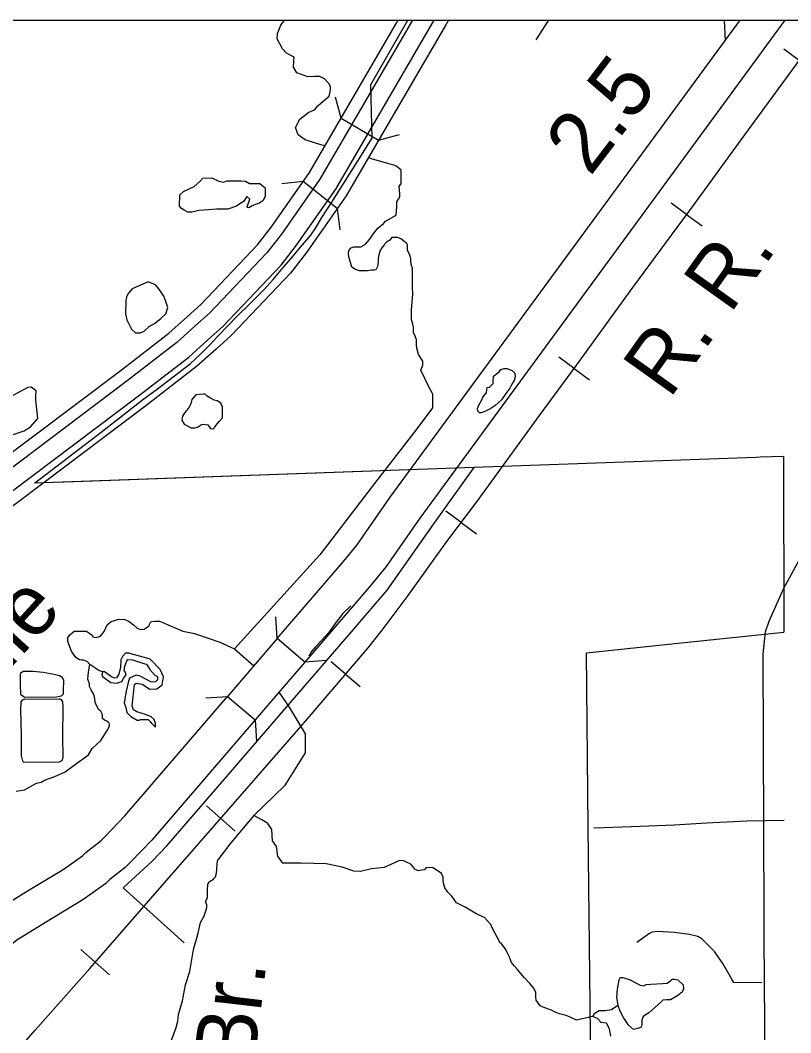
# Model space of a CAD drawing. Extents: x 1367863 to 1368197, y 380048 to 380261.
# Drawn here: x 1367991.45 to 1368012.13, y 380150.28 to 380177.46 of the extents above; entities that cross this region are included whole.
import ezdxf

# ---------------------------------------------------------------- set-up
doc = ezdxf.new("R2010")
doc.units = 0
for name, color, linetype in [('Level 10', 7, 'Continuous'), ('Level 15', 7, 'Continuous'), ('Level 33', 7, 'Continuous'), ('Level 35', 7, 'Continuous'), ('Level 36', 7, 'Continuous'), ('Level 37', 7, 'Continuous'), ('Level 40', 7, 'Continuous'), ('Level 48', 7, 'Continuous'), ('Level 6', 7, 'Continuous'), ('R_No Plot', 7, 'Continuous')]:
    doc.layers.add(name, color=color, linetype=linetype)

msp = doc.modelspace()

# ---------------------------------------------------------------- linework, layer by layer
at = {"layer": 'Level 10'}
for points in [[(1367998.348, 380160.867), (1368000.124, 380162.934), (1368000.494, 380163.382), (1368001.381, 380164.658), (1368010.775, 380177.46)], [(1368011.979, 380177.46), (1368002.171, 380164.093), (1368001.267, 380162.795), (1368000.866, 380162.309), (1367999.084, 380160.235)], [(1368011.429, 380151.097), (1368011.392, 380160.447), (1368011.452, 380161.041), (1368011.552, 380161.327), (1368011.947, 380162.215), (1368012.461, 380163.149), (1368012.59, 380163.421), (1368012.733, 380163.914), (1368013.259, 380165.995), (1368013.574, 380167.366), (1368013.883, 380168.861), (1368014.317, 380170.756)], [(1367998.348, 380160.867), (1367997.013, 380159.313)], [(1367999.084, 380160.235), (1367998.348, 380160.867)], [(1367999.084, 380160.235), (1367997.749, 380158.68)], [(1367988.776, 380151.732), (1367989.071, 380152.078), (1367989.492, 380152.486), (1367989.993, 380152.929), (1367990.793, 380153.566), (1367991.614, 380154.074), (1367992.598, 380154.665), (1367993.114, 380155.031), (1367993.202, 380155.12), (1367993.618, 380155.448), (1367993.715, 380155.544), (1367994.257, 380156.104), (1367997.013, 380159.313)], [(1367997.013, 380159.313), (1367997.749, 380158.68)], [(1367997.749, 380158.68), (1367994.975, 380155.45), (1367994.404, 380154.86), (1367994.26, 380154.719), (1367993.849, 380154.395), (1367993.743, 380154.288), (1367993.129, 380153.852), (1367992.119, 380153.246), (1367991.352, 380152.771), (1367990.618, 380152.186), (1367990.152, 380151.773), (1367989.78, 380151.413), (1367989.515, 380151.102)], [(1368011.429, 380151.098), (1368011.439, 380145.66), (1368011.416, 380141.25), (1368011.392, 380140.52), (1368011.431, 380140.222), (1368011.504, 380139.453), (1368011.603, 380138.92), (1368011.693, 380137.345), (1368011.778, 380132.275), (1368011.845, 380129.756)]]:
    msp.add_lwpolyline(points, dxfattribs=at)
at = {"layer": 'Level 15'}
for points in [[(1367983.775, 380160.267), (1367983.952, 380160.4), (1367986.169, 380162.096), (1367989.568, 380164.62), (1367994.115, 380168.041), (1367995.437, 380169.06), (1367995.925, 380169.499), (1367996.299, 380169.836), (1367997.817, 380171.432), (1367998.192, 380171.917), (1367999.213, 380173.375), (1368001.597, 380177.46)], [(1368001.979, 380177.46), (1367999.491, 380173.197), (1367998.457, 380171.722), (1367998.068, 380171.217), (1367996.529, 380169.599), (1367996.145, 380169.254), (1367995.648, 380168.807), (1367994.315, 380167.778), (1367989.766, 380164.356), (1367986.367, 380161.832), (1367984.151, 380160.136), (1367983.888, 380159.94)], [(1367984.089, 380159.461), (1367984.455, 380159.734), (1367986.671, 380161.43), (1367990.068, 380163.952), (1367994.62, 380167.377), (1367995.971, 380168.419), (1367996.483, 380168.878), (1367996.881, 380169.237), (1367998.451, 380170.888), (1367998.864, 380171.423), (1367999.916, 380172.924), (1368002.563, 380177.46)], [(1368002.944, 380177.46), (1368002.871, 380177.333), (1368000.194, 380172.746), (1367999.13, 380171.227), (1367998.702, 380170.673), (1367997.112, 380169.001), (1367996.703, 380168.633), (1367996.182, 380168.165), (1367994.82, 380167.114), (1367990.266, 380163.688), (1367986.87, 380161.166), (1367984.654, 380159.47), (1367984.225, 380159.15)]]:
    msp.add_lwpolyline(points, dxfattribs=at)
at = {"layer": 'Level 33'}
for points in [[(1368005.626, 380177.46), (1368005.286, 380176.932)], [(1368010.35, 380177.46), (1368010.37, 380176.908)], [(1368011.958, 380155.982), (1368010.959, 380155.964), (1368009.872, 380155.906), (1368009.011, 380155.859), (1368007.86, 380155.807), (1368006.842, 380155.778)], [(1368011.356, 380151.62), (1368010.605, 380151.631), (1368010.553, 380151.719), (1368010.314, 380152.143), (1368010.087, 380152.463), (1368009.75, 380152.806), (1368009.64, 380152.87), (1368009.413, 380152.917), (1368009, 380152.975), (1368008.564, 380153.004), (1368008.413, 380152.981), (1368008.32, 380152.94), (1368008.256, 380152.888), (1368008, 380152.708)]]:
    msp.add_lwpolyline(points, dxfattribs=at)
at = {"layer": 'Level 35'}
for points in [[(1367999.096, 380174.252), (1367998.908, 380174.382), (1367998.833, 380174.585), (1367998.951, 380174.809), (1367999.196, 380174.991), (1367999.325, 380175.044), (1367999.367, 380175.076), (1367999.432, 380175.162), (1367999.581, 380175.29), (1367999.741, 380175.418), (1367999.773, 380175.579), (1367999.773, 380175.685), (1367999.731, 380175.76), (1367999.613, 380175.889), (1367999.485, 380175.953), (1367999.335, 380175.953), (1367999.164, 380175.942), (1367998.876, 380176.049), (1367998.78, 380176.198), (1367998.791, 380176.359), (1367998.801, 380176.466), (1367998.598, 380176.573), (1367998.491, 380176.69), (1367998.342, 380176.957), (1367998.353, 380177.107), (1367998.438, 380177.331), (1367998.538, 380177.46)], [(1367999.62, 380174.089), (1367999.515, 380174.12), (1367999.096, 380174.252)], [(1368001.598, 380172.659), (1368001.639, 380172.72), (1368001.639, 380172.802), (1368001.618, 380173.006), (1368001.67, 380173.067), (1368001.67, 380173.2), (1368001.67, 380173.323), (1368001.67, 380173.435), (1368001.557, 380173.537), (1368001.506, 380173.558), (1368001.251, 380173.629), (1368000.904, 380173.731), (1368000.832, 380173.755)], [(1367997.527, 380172.726), (1367997.453, 380172.603), (1367997.25, 380172.472), (1367997.018, 380172.385), (1367996.916, 380172.385), (1367996.713, 380172.385), (1367996.503, 380172.371), (1367996.242, 380172.349), (1367996.054, 380172.313), (1367995.945, 380172.313), (1367995.843, 380172.364), (1367995.778, 380172.407), (1367995.72, 380172.472), (1367995.734, 380172.77), (1367995.829, 380172.864), (1367996.112, 380173.002), (1367996.264, 380173.133), (1367996.351, 380173.22), (1367996.59, 380173.227), (1367996.779, 380173.14), (1367996.902, 380173.118), (1367996.996, 380173.147), (1367997.149, 380173.147), (1367997.373, 380173.147), (1367997.497, 380173.14), (1367997.598, 380173.082), (1367997.656, 380173.082), (1367997.808, 380173.082), (1367997.881, 380173.075), (1367998.026, 380172.966), (1367998.026, 380172.842), (1367998.019, 380172.726), (1367997.961, 380172.617), (1367997.852, 380172.538), (1367997.75, 380172.516), (1367997.671, 380172.48), (1367997.584, 380172.429), (1367997.555, 380172.436), (1367997.54, 380172.465), (1367997.584, 380172.574), (1367997.613, 380172.654), (1367997.527, 380172.726)], [(1368002.517, 380167.441), (1368002.426, 380167.604), (1368002.201, 380168.072), (1368002.252, 380168.205), (1368002.252, 380168.307), (1368002.139, 380168.491), (1368002.098, 380168.654), (1368002.088, 380168.756), (1368002.088, 380168.879), (1368002.047, 380168.981), (1368002.007, 380169.083), (1368002.007, 380169.226), (1368001.976, 380169.339), (1368001.955, 380169.42), (1368001.955, 380169.553), (1368001.955, 380169.676), (1368001.986, 380170.115), (1368001.976, 380170.299), (1368001.976, 380170.401), (1368001.976, 380170.514), (1368001.976, 380170.616), (1368001.976, 380170.728), (1368001.976, 380170.81), (1368001.955, 380170.881), (1368001.935, 380170.973), (1368001.935, 380171.065), (1368001.904, 380171.157), (1368001.843, 380171.29), (1368001.843, 380171.361), (1368001.843, 380171.433), (1368001.812, 380171.484), (1368001.751, 380171.525), (1368001.68, 380171.586), (1368001.588, 380171.627), (1368001.527, 380171.627), (1368001.486, 380171.627), (1368001.424, 380171.627), (1368001.373, 380171.556), (1368001.281, 380171.504), (1368001.21, 380171.423), (1368001.108, 380171.29), (1368001.077, 380171.167), (1368001.057, 380171.065), (1368001.057, 380170.973), (1368001.036, 380170.851), (1368000.996, 380170.759), (1368000.944, 380170.748), (1368000.873, 380170.748), (1368000.771, 380170.738), (1368000.648, 380170.738), (1368000.556, 380170.738), (1368000.444, 380170.769), (1368000.352, 380170.83), (1368000.322, 380170.932), (1368000.271, 380171.106), (1368000.26, 380171.188), (1368000.271, 380171.28), (1368000.332, 380171.351), (1368000.403, 380171.382), (1368000.516, 380171.382), (1368000.587, 380171.382), (1368000.72, 380171.453), (1368000.822, 380171.576), (1368000.944, 380171.75), (1368001.047, 380171.882), (1368001.2, 380172.005), (1368001.251, 380172.066), (1368001.537, 380172.23), (1368001.557, 380172.454), (1368001.557, 380172.587), (1368001.598, 380172.659)], [(1367994.879, 380170.438), (1367994.451, 380170.249), (1367994.349, 380170.133), (1367994.299, 380170.032), (1367994.284, 380169.93), (1367994.27, 380169.582), (1367994.306, 380169.415), (1367994.429, 380169.169), (1367994.538, 380169.067), (1367994.676, 380169.067), (1367994.77, 380169.118), (1367994.908, 380169.241), (1367995.046, 380169.321), (1367995.22, 380169.459), (1367995.357, 380169.582), (1367995.408, 380169.749), (1367995.357, 380169.909), (1367995.299, 380170.054), (1367995.176, 380170.242), (1367995.075, 380170.358)], [(1367995.075, 380170.358), (1367994.879, 380170.438)], [(1368004.151, 380167.904), (1368004.314, 380168.034), (1368004.349, 380168.09), (1368004.435, 380168.116), (1368004.509, 380168.116), (1368004.656, 380168.057), (1368004.728, 380167.99), (1368004.73, 380167.89), (1368004.709, 380167.79), (1368004.644, 380167.688), (1368004.588, 380167.586), (1368004.486, 380167.444), (1368004.365, 380167.276), (1368004.291, 380167.202), (1368004.191, 380167.107), (1368004.082, 380167.042), (1368003.94, 380166.965), (1368003.833, 380166.921), (1368003.777, 380166.925), (1368003.728, 380166.967), (1368003.726, 380167.042), (1368003.759, 380167.132), (1368003.84, 380167.274), (1368003.868, 380167.344), (1368003.903, 380167.386), (1368003.961, 380167.46), (1368003.977, 380167.548), (1368003.986, 380167.602), (1368004.042, 380167.616), (1368004.093, 380167.653), (1368004.14, 380167.713), (1368004.142, 380167.762), (1368004.151, 380167.904)], [(1367990.803, 380167.13), (1367990.774, 380166.811), (1367990.847, 380166.637), (1367991.202, 380166.325), (1367991.55, 380166.441), (1367991.717, 380166.55), (1367991.92, 380166.767), (1367991.862, 380167.261), (1367991.862, 380167.391), (1367991.877, 380167.493), (1367991.869, 380167.515), (1367991.739, 380167.609), (1367991.652, 380167.602), (1367991.26, 380167.398), (1367991.035, 380167.268), (1367990.948, 380167.203), (1367990.803, 380167.13)], [(1367996.464, 380167.37), (1367996.407, 380167.423), (1367996.363, 380167.427), (1367996.242, 380167.415), (1367996.161, 380167.403), (1367996.052, 380167.281), (1367996.043, 380167.245), (1367996.023, 380167.168), (1367995.963, 380167.051), (1367995.902, 380166.978), (1367995.854, 380166.926), (1367995.805, 380166.837), (1367995.785, 380166.723), (1367995.845, 380166.618), (1367996.039, 380166.521), (1367996.14, 380166.521), (1367996.201, 380166.541), (1367996.31, 380166.606), (1367996.375, 380166.622), (1367996.48, 380166.602), (1367996.553, 380166.505), (1367996.642, 380166.493), (1367996.658, 380166.533), (1367996.71, 380166.594), (1367996.787, 380166.691), (1367996.872, 380166.792), (1367996.876, 380166.877), (1367996.872, 380166.966), (1367996.872, 380167.083), (1367996.828, 380167.18), (1367996.735, 380167.241), (1367996.654, 380167.265)], [(1367996.654, 380167.265), (1367996.557, 380167.314), (1367996.464, 380167.37)], [(1368002.517, 380167.441), (1368002.514, 380167.055), (1368002.091, 380166.492), (1368000.895, 380164.943), (1367999.487, 380163.112), (1367997.199, 380160.585)], [(1368000.319, 380161.744), (1368000.11, 380161.535), (1367999.873, 380161.232), (1367999.734, 380161.027), (1367999.525, 380160.804), (1367999.386, 380160.654), (1367999.267, 380160.514), (1367999.198, 380160.389)], [(1367993.277, 380157.741), (1367993.374, 380157.916), (1367993.612, 380158.129), (1367993.78, 380158.4), (1367993.838, 380158.516), (1367993.845, 380158.568), (1367993.825, 380158.606), (1367993.774, 380158.645), (1367993.709, 380158.671), (1367993.651, 380158.722), (1367993.651, 380158.8), (1367993.645, 380158.845), (1367993.606, 380158.916), (1367993.554, 380158.955), (1367993.496, 380159.071), (1367993.458, 380159.155), (1367993.445, 380159.239), (1367993.438, 380159.303), (1367993.412, 380159.381), (1367993.348, 380159.49), (1367993.309, 380159.581), (1367993.309, 380159.645), (1367993.258, 380159.774), (1367993.271, 380159.878), (1367993.29, 380160.02), (1367993.316, 380160.168), (1367993.238, 380160.245), (1367993.148, 380160.284), (1367993.103, 380160.284), (1367993.038, 380160.297), (1367992.935, 380160.355), (1367992.819, 380160.523), (1367992.722, 380160.781), (1367992.722, 380160.884), (1367992.78, 380160.962), (1367992.896, 380161.059), (1367993.025, 380161.059), (1367993.225, 380161.059), (1367993.374, 380160.955), (1367993.393, 380160.91), (1367993.483, 380160.897), (1367993.6, 380160.93), (1367993.703, 380161.052), (1367993.78, 380161.237), (1367993.89, 380161.321), (1367994.09, 380161.385), (1367994.251, 380161.379), (1367994.374, 380161.321), (1367994.49, 380161.237), (1367994.587, 380161.14), (1367994.677, 380161.108), (1367994.774, 380161.114), (1367994.903, 380161.204), (1367994.928, 380161.275), (1367994.974, 380161.321), (1367995.064, 380161.334), (1367995.187, 380161.334), (1367995.277, 380161.295), (1367995.496, 380161.198), (1367995.812, 380161.063), (1367996.122, 380160.998), (1367996.49, 380160.875), (1367996.806, 380160.766), (1367997.199, 380160.585), (1367997.716, 380160.131)], [(1367995.08, 380158.489), (1367995.077, 380158.586), (1367995.045, 380158.695), (1367994.961, 380158.766), (1367994.812, 380158.824), (1367994.574, 380158.895), (1367994.483, 380158.947), (1367994.451, 380159.063), (1367994.516, 380159.631), (1367994.561, 380159.663), (1367994.716, 380159.637), (1367994.928, 380159.508), (1367995.116, 380159.515), (1367995.258, 380159.625), (1367995.29, 380159.838), (1367995.206, 380160.031), (1367994.935, 380160.309), (1367994.78, 380160.36), (1367994.477, 380160.438), (1367994.374, 380160.476), (1367994.27, 380160.47), (1367994.187, 380160.38), (1367994.148, 380160.296), (1367994.135, 380160.096), (1367994.09, 380159.909), (1367994.032, 380159.812), (1367993.974, 380159.805), (1367993.896, 380159.838), (1367993.709, 380159.973), (1367993.651, 380159.973), (1367993.535, 380160.012), (1367993.477, 380160.057), (1367993.316, 380160.168)], [(1367993.651, 380159.973), (1367993.638, 380159.896), (1367993.658, 380159.844), (1367993.877, 380159.689), (1367994.038, 380159.67), (1367994.174, 380159.708), (1367994.225, 380159.812), (1367994.277, 380159.876), (1367994.277, 380159.921), (1367994.264, 380159.967), (1367994.232, 380159.986), (1367994.251, 380160.121), (1367994.303, 380160.27), (1367994.335, 380160.302), (1367994.458, 380160.296), (1367994.761, 380160.192), (1367994.832, 380160.173), (1367994.928, 380160.031), (1367995.058, 380159.883), (1367995.128, 380159.85), (1367995.135, 380159.754), (1367995.077, 380159.702), (1367995.019, 380159.696), (1367994.948, 380159.702), (1367994.664, 380159.857), (1367994.561, 380159.883), (1367994.477, 380159.844), (1367994.38, 380159.805), (1367994.348, 380159.721), (1367994.29, 380159.45), (1367994.238, 380159.141), (1367994.277, 380159.018), (1367994.309, 380158.882), (1367994.412, 380158.773), (1367994.587, 380158.676), (1367994.638, 380158.676), (1367994.67, 380158.689), (1367994.793, 380158.689), (1367994.877, 380158.689), (1367995.08, 380158.489), (1367994.941, 380158.624), (1367994.941, 380158.624)], [(1367991.557, 380159.285), (1367991.485, 380159.332), (1367991.459, 380159.358), (1367991.448, 380159.643), (1367991.448, 380159.909), (1367991.463, 380159.942), (1367991.522, 380159.987)], [(1367991.522, 380159.987), (1367991.793, 380159.987), (1367992.058, 380159.965), (1367992.359, 380159.908), (1367992.502, 380159.872)], [(1367992.502, 380159.872), (1367992.567, 380159.83), (1367992.604, 380159.751), (1367992.601, 380159.459), (1367992.597, 380159.369), (1367992.544, 380159.321), (1367992.423, 380159.292)], [(1367998.389, 380159.425), (1367998.669, 380159.027), (1367999.092, 380158.307), (1367999.092, 380157.799), (1367998.542, 380156.909), (1367997.716, 380156.116), (1367997.102, 380155.383), (1367996.749, 380154.925)], [(1367991.572, 380159.235), (1367991.496, 380159.212), (1367991.463, 380159.167), (1367991.455, 380158.946), (1367991.474, 380158.283), (1367991.474, 380157.718), (1367991.493, 380157.609), (1367991.526, 380157.557), (1367991.543, 380157.545)], [(1367992.423, 380159.292), (1367991.557, 380159.285)], [(1367991.572, 380159.235), (1367992.495, 380159.242)], [(1367992.502, 380157.552), (1367992.571, 380157.59), (1367992.597, 380157.68), (1367992.593, 380158.227), (1367992.601, 380159.032), (1367992.589, 380159.167), (1367992.556, 380159.216), (1367992.495, 380159.242)], [(1367991.335, 380156.767), (1367991.561, 380156.806), (1367991.884, 380156.986), (1367992.006, 380157.012), (1367992.096, 380157.064), (1367992.374, 380157.161), (1367992.651, 380157.283), (1367992.896, 380157.464), (1367993.277, 380157.741)], [(1367991.543, 380157.545), (1367992.502, 380157.552)], [(1368007.301, 380150.194), (1368007.264, 380150.387), (1368007.188, 380150.539), (1368007.112, 380150.55), (1368007.047, 380150.561), (1368006.949, 380150.67), (1368006.808, 380150.724), (1368006.385, 380150.626), (1368006.233, 380150.691), (1368006.102, 380150.746), (1368005.994, 380150.778), (1368005.929, 380150.789), (1368005.809, 380150.833), (1368005.712, 380150.887), (1368005.625, 380150.92), (1368005.484, 380150.974), (1368005.408, 380151.006), (1368005.299, 380151.158), (1368005.288, 380151.245), (1368005.288, 380151.365), (1368005.234, 380151.484), (1368005.125, 380151.604), (1368004.984, 380151.756), (1368004.887, 380151.875), (1368004.8, 380151.984), (1368004.724, 380152.06), (1368004.637, 380152.168), (1368004.583, 380152.309), (1368004.528, 380152.418), (1368004.485, 380152.516), (1368004.355, 380152.69), (1368004.333, 380152.7), (1368004.116, 380153.102), (1368004.083, 380153.189), (1368003.91, 380153.374), (1368003.703, 380153.471), (1368003.389, 380153.656), (1368003.161, 380153.775), (1368003.03, 380153.949), (1368002.922, 380154.058), (1368002.846, 380154.177), (1368002.813, 380154.297), (1368002.803, 380154.383), (1368002.803, 380154.459), (1368002.759, 380154.557), (1368002.531, 380154.709), (1368002.347, 380154.72), (1368002.303, 380154.655), (1368002.216, 380154.644), (1368002.13, 380154.633), (1368002.043, 380154.677), (1368001.988, 380154.742), (1368001.934, 380154.807), (1368001.717, 380154.905), (1368001.609, 380154.894), (1368001.218, 380154.72), (1368000.881, 380154.688), (1368000.577, 380154.612), (1368000.404, 380154.622), (1368000.089, 380154.731), (1367999.655, 380154.818), (1367998.982, 380154.84), (1367998.493, 380154.84), (1367998.363, 380155.024), (1367998.33, 380155.285), (1367998.222, 380155.437), (1367998.2, 380155.741), (1367998.092, 380155.904), (1367997.929, 380156.001), (1367997.716, 380156.116)], [(1367995.509, 380150.087), (1367995.635, 380150.426), (1367995.676, 380150.594), (1367995.697, 380150.774), (1367995.802, 380151.143), (1367995.882, 380151.566), (1367995.999, 380151.926), (1367996.053, 380152.253), (1367996.095, 380152.517), (1367996.212, 380152.923), (1367996.288, 380153.246), (1367996.38, 380153.426), (1367996.413, 380153.502), (1367996.434, 380153.585), (1367996.455, 380153.648), (1367996.451, 380153.715), (1367996.422, 380153.803), (1367996.476, 380153.904), (1367996.476, 380154.038), (1367996.476, 380154.088), (1367996.476, 380154.155), (1367996.48, 380154.222), (1367996.48, 380154.268), (1367996.514, 380154.339), (1367996.556, 380154.365), (1367996.614, 380154.39), (1367996.648, 380154.436), (1367996.69, 380154.465), (1367996.719, 380154.57), (1367996.723, 380154.666), (1367996.732, 380154.825), (1367996.749, 380154.925)], [(1368007.522, 380151.694), (1368007.552, 380151.764), (1368007.627, 380151.764), (1368007.819, 380151.7), (1368008.092, 380151.56), (1368008.18, 380151.543), (1368008.244, 380151.572), (1368008.244, 380151.578), (1368008.377, 380151.584), (1368008.691, 380151.607), (1368008.819, 380151.619), (1368008.901, 380151.677), (1368008.953, 380151.723), (1368009.011, 380151.723), (1368009.098, 380151.7), (1368009.244, 380151.566), (1368009.255, 380151.461), (1368009.215, 380151.374), (1368009.098, 380151.281), (1368008.906, 380151.165), (1368008.796, 380151.165), (1368008.703, 380151.159), (1368008.645, 380151.101), (1368008.325, 380150.822), (1368008.174, 380150.723), (1368008.133, 380150.618), (1368008.133, 380150.502), (1368008.116, 380150.432), (1368008.052, 380150.403), (1368007.912, 380150.368)], [(1368007.522, 380151.694), (1368007.476, 380151.45), (1368007.458, 380151.252), (1368007.493, 380151.019), (1368007.557, 380150.851), (1368007.65, 380150.67), (1368007.761, 380150.502), (1368007.912, 380150.368)], [(1368007.493, 380151.019), (1368007.318, 380150.898), (1368007.155, 380150.876), (1368006.992, 380150.876), (1368006.851, 380150.789), (1368006.808, 380150.724)]]:
    msp.add_lwpolyline(points, dxfattribs=at)
at = {"layer": 'Level 36'}
for p, q in [((1368000.061, 380174.828), (1367999.913, 380175.391)), ((1368000.061, 380174.828), (1368001.067, 380174.241)), ((1368001.067, 380174.241), (1368001.63, 380174.389)), ((1367999.046, 380173.135), (1367998.468, 380173.068)), ((1367999.958, 380172.411), (1367999.046, 380173.135)), ((1367999.958, 380172.411), (1368000.025, 380171.833))]:
    msp.add_line(p, q, dxfattribs=at)
at = {"layer": 'Level 37'}
for points in [[(1367998.348, 380160.867), (1367998.304, 380161.448)], [(1367999.665, 380160.279), (1367999.084, 380160.235)], [(1367996.432, 380159.269), (1367997.013, 380159.313)], [(1367997.749, 380158.68), (1367997.793, 380158.1)]]:
    msp.add_lwpolyline(points, dxfattribs=at)
at = {"layer": 'Level 40'}
for p, q in [((1368012.364, 380176.381), (1368011.951, 380176.684)), ((1368009.339, 380172.247), (1368008.926, 380172.55)), ((1368009.339, 380172.247), (1368009.752, 380171.943)), ((1368006.316, 380168.11), (1368005.905, 380168.416)), ((1368006.316, 380168.11), (1368006.728, 380167.805)), ((1368003.287, 380163.979), (1368002.876, 380164.285)), ((1368003.287, 380163.979), (1368003.698, 380163.673)), ((1368000.181, 380159.908), (1367999.792, 380160.241)), ((1368000.181, 380159.908), (1368000.571, 380159.575)), ((1367996.828, 380156.035), (1367996.443, 380156.373)), ((1367996.828, 380156.035), (1367997.213, 380155.697)), ((1367993.456, 380152.178), (1367993.07, 380152.515)), ((1367993.456, 380152.178), (1367993.842, 380151.841))]:
    msp.add_line(p, q, dxfattribs=at)
for points in [[(1367989.355, 380147.507), (1367991.846, 380150.349), (1367993.31, 380152.01), (1367995.255, 380154.24), (1367997.659, 380156.983), (1367999.101, 380158.645), (1368000.784, 380160.612), (1368001.166, 380161.093), (1368001.865, 380162.022), (1368002.903, 380163.465), (1368003.701, 380164.536), (1368005.384, 380166.853), (1368006.389, 380168.208), (1368007.897, 380170.285), (1368009.536, 380172.515), (1368010.803, 380174.253), (1368012.366, 380176.384), (1368013.156, 380177.46)], [(1367989.355, 380147.507), (1367991.846, 380150.349), (1367993.31, 380152.01), (1367995.255, 380154.24), (1367997.659, 380156.983), (1367999.101, 380158.645), (1368000.784, 380160.612), (1368001.166, 380161.093), (1368001.865, 380162.022), (1368002.903, 380163.465), (1368003.701, 380164.536), (1368005.384, 380166.853), (1368006.389, 380168.208), (1368007.897, 380170.285), (1368009.536, 380172.515), (1368010.803, 380174.253), (1368012.366, 380176.384)]]:
    msp.add_lwpolyline(points, dxfattribs=at)
at = {"layer": 'Level 6'}
for points in [[(1368000.846, 380175.715), (1368001.856, 380177.46)], [(1368000.846, 380175.715), (1368000.89, 380174.287)], [(1367991.83, 380165.034), (1367993.618, 380166.406), (1367994.73, 380167.271), (1367995.135, 380167.566), (1367996.012, 380168.242), (1367996.283, 380168.501), (1367996.527, 380168.735), (1367996.763, 380168.988), (1367997.014, 380169.246), (1367997.265, 380169.508), (1367997.64, 380169.875), (1367997.997, 380170.234), (1367998.236, 380170.503), (1367998.459, 380170.771), (1367998.713, 380171.06), (1367998.974, 380171.373), (1367999.246, 380171.694), (1367999.379, 380171.889), (1367999.541, 380172.163), (1367999.813, 380172.581), (1368000.608, 380173.84), (1368000.89, 380174.287)], [(1368011.317, 380165.732), (1368011.193, 380165.727), (1368003.636, 380165.457)], [(1368011.942, 380165.747), (1368011.317, 380165.732)], [(1368011.942, 380165.747), (1368011.947, 380161.037)], [(1368003.636, 380165.457), (1367991.83, 380165.034)], [(1368003.636, 380165.457), (1367992.376, 380165.054)], [(1367994.21, 380154.178), (1367994.985, 380154.888), (1367995.379, 380155.3), (1367997.035, 380157.216), (1367998.646, 380159.088), (1368000.392, 380161.111), (1368001.296, 380162.159), (1368002.549, 380163.941), (1368003.516, 380165.293), (1368003.636, 380165.457)], [(1368006.652, 380160.477), (1368008.848, 380160.714), (1368010.659, 380160.9), (1368011.947, 380161.037)], [(1368006.692, 380155.797), (1368006.652, 380160.477)], [(1368006.812, 380145.508), (1368006.692, 380155.797)], [(1367994.21, 380154.178), (1367995.849, 380152.696)]]:
    msp.add_lwpolyline(points, dxfattribs=at)
at = {"layer": 'R_No Plot'}
msp.add_lwpolyline([(1367959.444, 380177.46), (1368103.344, 380177.46), (1368103.344, 380096.865), (1367959.444, 380096.865)], close=True, dxfattribs=at)

# ---------------------------------------------------------------- texts
at = {"layer": 'Level 35'}
for s, rotation, p in [('Fourmile', 47.5543, (1367986.857, 380155.33)), ('Br.', 83.289, (1367997.728, 380149.365))]:
    msp.add_text(s, height=1.6394, rotation=rotation, dxfattribs=at).set_placement(p)
at = {"layer": 'Level 40'}
msp.add_text('R. R.', height=1.6394, rotation=54.5264, dxfattribs=at).set_placement((1368008.877, 380167.269))
at = {"layer": 'Level 48'}
msp.add_text('2.5', height=1.6394, rotation=52.5766, dxfattribs=at).set_placement((1368006.743, 380173.245))

doc.saveas('drawing.dxf')
